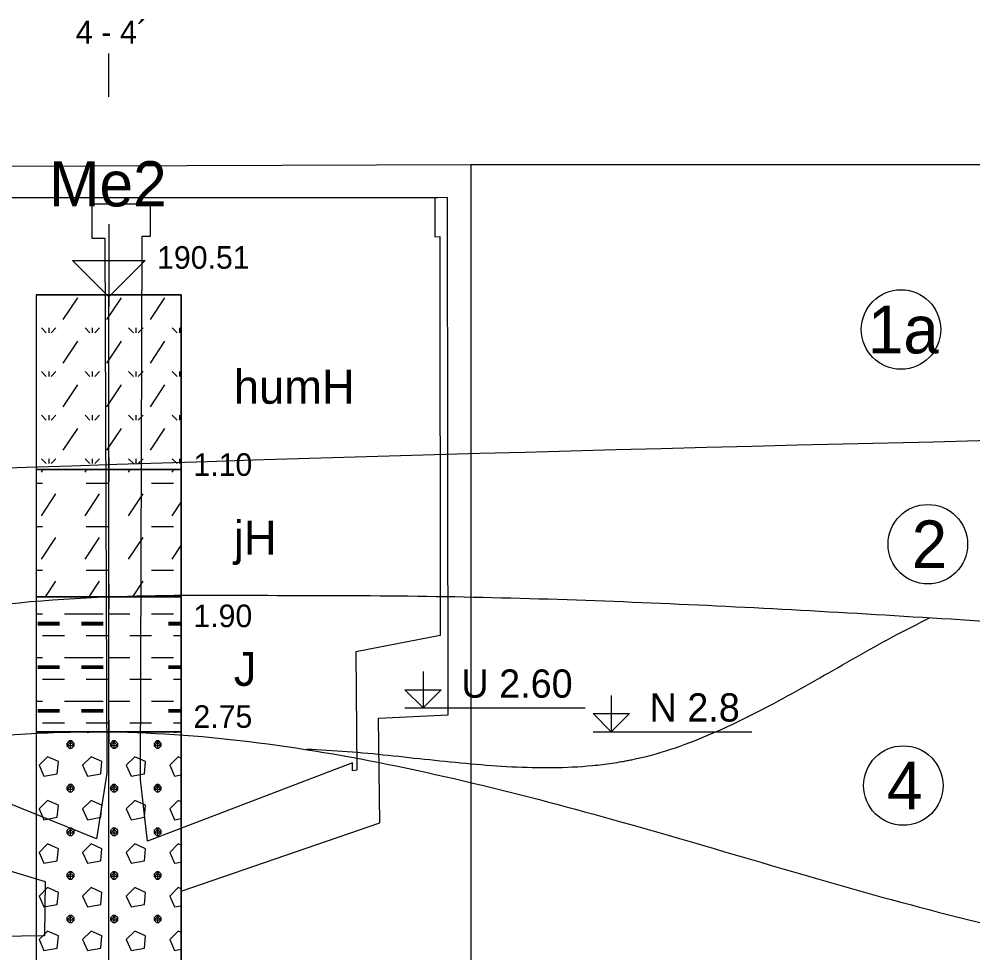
# Model space of a CAD drawing. Extents: x 3042 to 4120, y 576 to 2694.
# Drawn here: x 3378.17 to 3408.18, y 1288.39 to 1317.77 of the extents above; entities that cross this region are included whole.
import ezdxf

# ---------------------------------------------------------------- set-up
doc = ezdxf.new("R2010")
doc.units = 0
for name, color, linetype in [('15', 7, 'Continuous'), ('16', 7, 'Continuous'), ('17', 7, 'Continuous'), ('18', 7, 'Continuous'), ('22', 7, 'Continuous'), ('51', 7, 'Continuous'), ('52', 7, 'Continuous'), ('53', 7, 'Continuous'), ('56', 7, 'Continuous'), ('61', 7, 'Continuous'), ('komunikace', 7, 'Continuous'), ('nádrže', 7, 'Continuous'), ('pomocna', 7, 'Continuous'), ('rozhraní', 7, 'Continuous')]:
    doc.layers.add(name, color=color, linetype=linetype)

msp = doc.modelspace()

# ---------------------------------------------------------------- linework, layer by layer
at = {"layer": '15'}
msp.add_lwpolyline([(3380.987, 1311.318), (3380.987, 1309.032), (3379.844, 1310.175), (3382.13, 1310.175), (3380.987, 1309.032)], dxfattribs=at)
at = {"layer": '18'}
msp.add_line((3380.987, 1272.595), (3380.987, 1309.095), dxfattribs=at)
at = {"layer": '22'}
msp.add_lwpolyline([(3380.987, 1315.318), (3380.987, 1315.318), (3380.987, 1316.687)], dxfattribs=at)
at = {"layer": '51'}
for p, q in [((3379.557, 1308.316), (3380.014, 1309.002)), ((3380.928, 1308.316), (3381.386, 1309.002)), ((3382.3, 1308.316), (3382.757, 1309.002)), ((3378.871, 1308.049), (3379.023, 1307.897)), ((3379.1, 1308.049), (3379.1, 1307.897)), ((3379.328, 1308.049), (3379.176, 1307.897)), ((3380.243, 1308.049), (3380.395, 1307.897)), ((3380.471, 1308.049), (3380.471, 1307.897)), ((3380.7, 1308.049), (3380.547, 1307.897)), ((3381.614, 1308.049), (3381.767, 1307.897)), ((3381.843, 1308.049), (3381.843, 1307.897)), ((3382.071, 1308.049), (3381.919, 1307.897)), ((3382.986, 1308.049), (3383.138, 1307.897)), ((3383.214, 1308.049), (3383.214, 1307.897)), ((3379.557, 1306.944), (3380.014, 1307.63)), ((3380.928, 1306.944), (3381.386, 1307.63)), ((3382.3, 1306.944), (3382.757, 1307.63)), ((3378.871, 1306.678), (3379.023, 1306.525)), ((3379.1, 1306.678), (3379.1, 1306.525)), ((3379.328, 1306.678), (3379.176, 1306.525)), ((3380.243, 1306.678), (3380.395, 1306.525)), ((3380.471, 1306.678), (3380.471, 1306.525)), ((3380.7, 1306.678), (3380.547, 1306.525)), ((3381.614, 1306.678), (3381.767, 1306.525)), ((3381.843, 1306.678), (3381.843, 1306.525)), ((3382.071, 1306.678), (3381.919, 1306.525)), ((3382.986, 1306.678), (3383.138, 1306.525)), ((3383.214, 1306.678), (3383.214, 1306.525)), ((3379.557, 1305.573), (3380.014, 1306.258)), ((3380.928, 1305.573), (3381.386, 1306.258)), ((3382.3, 1305.573), (3382.757, 1306.258)), ((3378.871, 1305.306), (3379.023, 1305.154)), ((3379.1, 1305.306), (3379.1, 1305.154)), ((3379.328, 1305.306), (3379.176, 1305.154)), ((3380.243, 1305.306), (3380.395, 1305.154)), ((3380.471, 1305.306), (3380.471, 1305.154)), ((3380.7, 1305.306), (3380.547, 1305.154)), ((3381.614, 1305.306), (3381.767, 1305.154)), ((3381.843, 1305.306), (3381.843, 1305.154)), ((3382.071, 1305.306), (3381.919, 1305.154)), ((3382.986, 1305.306), (3383.138, 1305.154)), ((3383.214, 1305.306), (3383.214, 1305.154)), ((3379.557, 1304.201), (3380.014, 1304.887)), ((3380.928, 1304.201), (3381.386, 1304.887)), ((3382.3, 1304.201), (3382.757, 1304.887)), ((3378.871, 1303.934), (3379.023, 1303.782)), ((3379.1, 1303.934), (3379.1, 1303.782)), ((3379.328, 1303.934), (3379.176, 1303.782)), ((3380.243, 1303.934), (3380.395, 1303.782)), ((3380.471, 1303.934), (3380.471, 1303.782)), ((3380.7, 1303.934), (3380.547, 1303.782)), ((3381.614, 1303.934), (3381.767, 1303.782)), ((3381.843, 1303.934), (3381.843, 1303.782)), ((3382.071, 1303.934), (3381.919, 1303.782)), ((3382.986, 1303.934), (3383.138, 1303.782)), ((3383.214, 1303.934), (3383.214, 1303.782)), ((3378.871, 1303.515), (3378.924, 1303.595)), ((3380.243, 1303.515), (3380.296, 1303.595)), ((3381.614, 1303.515), (3381.668, 1303.595)), ((3382.986, 1303.515), (3383.039, 1303.595)), ((3378.701, 1303.172), (3378.909, 1303.172)), ((3380.281, 1303.172), (3380.967, 1303.172)), ((3382.338, 1303.172), (3383.024, 1303.172)), ((3378.871, 1302.144), (3379.328, 1302.829)), ((3380.243, 1302.144), (3380.7, 1302.829)), ((3381.614, 1302.144), (3382.071, 1302.829)), ((3382.986, 1302.144), (3383.273, 1302.574)), ((3378.701, 1301.801), (3378.909, 1301.801)), ((3380.281, 1301.801), (3380.967, 1301.801)), ((3382.338, 1301.801), (3383.024, 1301.801)), ((3378.871, 1300.772), (3379.328, 1301.458)), ((3380.243, 1300.772), (3380.7, 1301.458)), ((3381.614, 1300.772), (3382.071, 1301.458)), ((3382.986, 1300.772), (3383.273, 1301.202)), ((3378.701, 1300.429), (3378.909, 1300.429)), ((3380.281, 1300.429), (3380.967, 1300.429)), ((3382.338, 1300.429), (3383.024, 1300.429)), ((3379.001, 1299.595), (3379.328, 1300.086)), ((3380.373, 1299.595), (3380.7, 1300.086)), ((3381.744, 1299.595), (3382.071, 1300.086)), ((3378.701, 1299.058), (3378.909, 1299.058)), ((3379.595, 1299.058), (3380.281, 1299.058)), ((3380.128, 1299.058), (3380.814, 1299.058)), ((3380.967, 1299.058), (3381.652, 1299.058)), ((3382.338, 1299.058), (3383.024, 1299.058)), ((3378.757, 1298.791), (3379.443, 1298.791)), ((3378.757, 1298.753), (3379.443, 1298.753)), ((3378.757, 1298.715), (3379.443, 1298.715)), ((3380.128, 1298.791), (3380.814, 1298.791)), ((3380.128, 1298.753), (3380.814, 1298.753)), ((3380.128, 1298.715), (3380.814, 1298.715)), ((3382.872, 1298.791), (3383.273, 1298.791)), ((3382.872, 1298.753), (3383.273, 1298.753)), ((3382.872, 1298.715), (3383.273, 1298.715)), ((3378.909, 1298.372), (3379.595, 1298.372)), ((3380.281, 1298.372), (3380.967, 1298.372)), ((3381.652, 1298.372), (3382.338, 1298.372)), ((3383.024, 1298.372), (3383.273, 1298.372)), ((3378.701, 1297.686), (3378.909, 1297.686)), ((3379.595, 1297.686), (3380.281, 1297.686)), ((3380.128, 1297.686), (3380.814, 1297.686)), ((3380.967, 1297.686), (3381.652, 1297.686)), ((3382.338, 1297.686), (3383.024, 1297.686)), ((3378.757, 1297.419), (3379.443, 1297.419)), ((3378.757, 1297.381), (3379.443, 1297.381)), ((3378.757, 1297.343), (3379.443, 1297.343)), ((3380.128, 1297.419), (3380.814, 1297.419)), ((3380.128, 1297.381), (3380.814, 1297.381)), ((3380.128, 1297.343), (3380.814, 1297.343)), ((3382.872, 1297.419), (3383.273, 1297.419)), ((3382.872, 1297.381), (3383.273, 1297.381)), ((3382.872, 1297.343), (3383.273, 1297.343)), ((3378.909, 1297), (3379.595, 1297)), ((3380.281, 1297), (3380.967, 1297)), ((3381.652, 1297), (3382.338, 1297)), ((3383.024, 1297), (3383.273, 1297)), ((3378.701, 1296.314), (3378.909, 1296.314)), ((3379.595, 1296.314), (3380.281, 1296.314)), ((3380.128, 1296.314), (3380.814, 1296.314)), ((3380.967, 1296.314), (3381.652, 1296.314)), ((3382.338, 1296.314), (3383.024, 1296.314)), ((3378.757, 1296.048), (3379.443, 1296.048)), ((3378.757, 1296.01), (3379.443, 1296.01)), ((3380.128, 1296.048), (3380.814, 1296.048)), ((3380.128, 1296.01), (3380.814, 1296.01)), ((3382.872, 1296.048), (3383.273, 1296.048)), ((3382.872, 1296.01), (3383.273, 1296.01)), ((3378.757, 1295.971), (3379.443, 1295.971)), ((3380.128, 1295.971), (3380.814, 1295.971)), ((3382.872, 1295.971), (3383.273, 1295.971)), ((3378.909, 1295.629), (3379.595, 1295.629)), ((3380.281, 1295.629), (3380.967, 1295.629)), ((3381.652, 1295.629), (3382.338, 1295.629)), ((3383.024, 1295.629), (3383.273, 1295.629)), ((3379.785, 1294.828), (3379.785, 1295.057)), ((3381.157, 1294.828), (3381.157, 1295.057)), ((3382.529, 1294.828), (3382.529, 1295.057)), ((3379.785, 1293.457), (3379.785, 1293.685)), ((3381.157, 1293.457), (3381.157, 1293.685)), ((3382.529, 1293.457), (3382.529, 1293.685)), ((3379.785, 1292.085), (3379.785, 1292.314)), ((3381.157, 1292.085), (3381.157, 1292.314)), ((3382.529, 1292.085), (3382.529, 1292.314)), ((3379.785, 1290.714), (3379.785, 1290.942)), ((3381.157, 1290.714), (3381.157, 1290.942)), ((3382.529, 1290.714), (3382.529, 1290.942)), ((3379.785, 1289.342), (3379.785, 1289.571)), ((3381.157, 1289.342), (3381.157, 1289.571)), ((3382.529, 1289.342), (3382.529, 1289.571))]:
    msp.add_line(p, q, dxfattribs=at)
for points in [[(3378.701, 1303.595), (3383.273, 1303.595), (3383.273, 1309.095), (3378.701, 1309.095)], [(3378.701, 1299.595), (3383.273, 1299.595), (3383.273, 1303.595), (3378.701, 1303.595)], [(3378.701, 1295.345), (3383.273, 1295.345), (3383.273, 1299.595), (3378.701, 1299.595)], [(3378.701, 1277.595), (3383.273, 1277.595), (3383.273, 1295.345), (3378.701, 1295.345)]]:
    msp.add_lwpolyline(points, close=True, dxfattribs=at)
for points in [[(3378.938, 1295.345), (3378.947, 1295.324), (3379.066, 1295.345)], [(3380.309, 1295.345), (3380.319, 1295.324), (3380.438, 1295.345)], [(3381.681, 1295.345), (3381.69, 1295.324), (3381.81, 1295.345)], [(3383.052, 1295.345), (3383.062, 1295.324), (3383.181, 1295.345)], [(3379.747, 1295.057), (3379.671, 1294.981), (3379.671, 1294.905), (3379.747, 1294.828), (3379.824, 1294.828), (3379.9, 1294.905), (3379.9, 1294.981), (3379.824, 1295.057), (3379.747, 1295.057), (3379.9, 1294.905), (3379.671, 1294.905), (3379.824, 1295.057)], [(3381.119, 1295.057), (3381.043, 1294.981), (3381.043, 1294.905), (3381.119, 1294.828), (3381.195, 1294.828), (3381.271, 1294.905), (3381.271, 1294.981), (3381.195, 1295.057), (3381.119, 1295.057), (3381.271, 1294.905), (3381.043, 1294.905), (3381.195, 1295.057)], [(3382.491, 1295.057), (3382.414, 1294.981), (3382.414, 1294.905), (3382.491, 1294.828), (3382.567, 1294.828), (3382.643, 1294.905), (3382.643, 1294.981), (3382.567, 1295.057), (3382.491, 1295.057), (3382.643, 1294.905), (3382.414, 1294.905), (3382.567, 1295.057)], [(3378.795, 1294.295), (3378.947, 1293.952), (3379.366, 1294.028), (3379.404, 1294.409), (3379.062, 1294.562), (3378.795, 1294.295)], [(3380.166, 1294.295), (3380.319, 1293.952), (3380.738, 1294.028), (3380.776, 1294.409), (3380.433, 1294.562), (3380.166, 1294.295)], [(3381.538, 1294.295), (3381.69, 1293.952), (3382.11, 1294.028), (3382.148, 1294.409), (3381.805, 1294.562), (3381.538, 1294.295)], [(3383.273, 1294.519), (3383.176, 1294.562), (3382.91, 1294.295)], [(3382.91, 1294.295), (3383.062, 1293.952), (3383.273, 1293.99)], [(3379.747, 1293.685), (3379.671, 1293.609), (3379.671, 1293.533), (3379.747, 1293.457), (3379.824, 1293.457), (3379.9, 1293.533), (3379.9, 1293.609), (3379.824, 1293.685), (3379.747, 1293.685), (3379.9, 1293.533), (3379.671, 1293.533), (3379.824, 1293.685)], [(3381.119, 1293.685), (3381.043, 1293.609), (3381.043, 1293.533), (3381.119, 1293.457), (3381.195, 1293.457), (3381.271, 1293.533), (3381.271, 1293.609), (3381.195, 1293.685), (3381.119, 1293.685), (3381.271, 1293.533), (3381.043, 1293.533), (3381.195, 1293.685)], [(3382.491, 1293.685), (3382.414, 1293.609), (3382.414, 1293.533), (3382.491, 1293.457), (3382.567, 1293.457), (3382.643, 1293.533), (3382.643, 1293.609), (3382.567, 1293.685), (3382.491, 1293.685), (3382.643, 1293.533), (3382.414, 1293.533), (3382.567, 1293.685)], [(3378.795, 1292.923), (3378.947, 1292.581), (3379.366, 1292.657), (3379.404, 1293.038), (3379.062, 1293.19), (3378.795, 1292.923)], [(3380.166, 1292.923), (3380.319, 1292.581), (3380.738, 1292.657), (3380.776, 1293.038), (3380.433, 1293.19), (3380.166, 1292.923)], [(3381.538, 1292.923), (3381.69, 1292.581), (3382.11, 1292.657), (3382.148, 1293.038), (3381.805, 1293.19), (3381.538, 1292.923)], [(3383.273, 1293.147), (3383.176, 1293.19), (3382.91, 1292.923)], [(3382.91, 1292.923), (3383.062, 1292.581), (3383.273, 1292.619)], [(3379.747, 1292.314), (3379.671, 1292.238), (3379.671, 1292.161), (3379.747, 1292.085), (3379.824, 1292.085), (3379.9, 1292.161), (3379.9, 1292.238), (3379.824, 1292.314), (3379.747, 1292.314), (3379.9, 1292.161), (3379.671, 1292.161), (3379.824, 1292.314)], [(3381.119, 1292.314), (3381.043, 1292.238), (3381.043, 1292.161), (3381.119, 1292.085), (3381.195, 1292.085), (3381.271, 1292.161), (3381.271, 1292.238), (3381.195, 1292.314), (3381.119, 1292.314), (3381.271, 1292.161), (3381.043, 1292.161), (3381.195, 1292.314)], [(3382.491, 1292.314), (3382.414, 1292.238), (3382.414, 1292.161), (3382.491, 1292.085), (3382.567, 1292.085), (3382.643, 1292.161), (3382.643, 1292.238), (3382.567, 1292.314), (3382.491, 1292.314), (3382.643, 1292.161), (3382.414, 1292.161), (3382.567, 1292.314)], [(3378.795, 1291.552), (3378.947, 1291.209), (3379.366, 1291.285), (3379.404, 1291.666), (3379.062, 1291.819), (3378.795, 1291.552)], [(3380.166, 1291.552), (3380.319, 1291.209), (3380.738, 1291.285), (3380.776, 1291.666), (3380.433, 1291.819), (3380.166, 1291.552)], [(3381.538, 1291.552), (3381.69, 1291.209), (3382.11, 1291.285), (3382.148, 1291.666), (3381.805, 1291.819), (3381.538, 1291.552)], [(3383.273, 1291.776), (3383.176, 1291.819), (3382.91, 1291.552)], [(3382.91, 1291.552), (3383.062, 1291.209), (3383.273, 1291.247)], [(3379.747, 1290.942), (3379.671, 1290.866), (3379.671, 1290.79), (3379.747, 1290.714), (3379.824, 1290.714), (3379.9, 1290.79), (3379.9, 1290.866), (3379.824, 1290.942), (3379.747, 1290.942), (3379.9, 1290.79), (3379.671, 1290.79), (3379.824, 1290.942)], [(3381.119, 1290.942), (3381.043, 1290.866), (3381.043, 1290.79), (3381.119, 1290.714), (3381.195, 1290.714), (3381.271, 1290.79), (3381.271, 1290.866), (3381.195, 1290.942), (3381.119, 1290.942), (3381.271, 1290.79), (3381.043, 1290.79), (3381.195, 1290.942)], [(3382.491, 1290.942), (3382.414, 1290.866), (3382.414, 1290.79), (3382.491, 1290.714), (3382.567, 1290.714), (3382.643, 1290.79), (3382.643, 1290.866), (3382.567, 1290.942), (3382.491, 1290.942), (3382.643, 1290.79), (3382.414, 1290.79), (3382.567, 1290.942)], [(3378.795, 1290.18), (3378.947, 1289.837), (3379.366, 1289.914), (3379.404, 1290.295), (3379.062, 1290.447), (3378.795, 1290.18)], [(3380.166, 1290.18), (3380.319, 1289.837), (3380.738, 1289.914), (3380.776, 1290.295), (3380.433, 1290.447), (3380.166, 1290.18)], [(3381.538, 1290.18), (3381.69, 1289.837), (3382.11, 1289.914), (3382.148, 1290.295), (3381.805, 1290.447), (3381.538, 1290.18)], [(3383.273, 1290.404), (3383.176, 1290.447), (3382.91, 1290.18)], [(3382.91, 1290.18), (3383.062, 1289.837), (3383.273, 1289.876)], [(3379.747, 1289.571), (3379.671, 1289.494), (3379.671, 1289.418), (3379.747, 1289.342), (3379.824, 1289.342), (3379.9, 1289.418), (3379.9, 1289.494), (3379.824, 1289.571), (3379.747, 1289.571), (3379.9, 1289.418), (3379.671, 1289.418), (3379.824, 1289.571)], [(3381.119, 1289.571), (3381.043, 1289.494), (3381.043, 1289.418), (3381.119, 1289.342), (3381.195, 1289.342), (3381.271, 1289.418), (3381.271, 1289.494), (3381.195, 1289.571), (3381.119, 1289.571), (3381.271, 1289.418), (3381.043, 1289.418), (3381.195, 1289.571)], [(3382.491, 1289.571), (3382.414, 1289.494), (3382.414, 1289.418), (3382.491, 1289.342), (3382.567, 1289.342), (3382.643, 1289.418), (3382.643, 1289.494), (3382.567, 1289.571), (3382.491, 1289.571), (3382.643, 1289.418), (3382.414, 1289.418), (3382.567, 1289.571)], [(3378.795, 1288.809), (3378.947, 1288.466), (3379.366, 1288.542), (3379.404, 1288.923), (3379.062, 1289.075), (3378.795, 1288.809)], [(3380.166, 1288.809), (3380.319, 1288.466), (3380.738, 1288.542), (3380.776, 1288.923), (3380.433, 1289.075), (3380.166, 1288.809)], [(3381.538, 1288.809), (3381.69, 1288.466), (3382.11, 1288.542), (3382.148, 1288.923), (3381.805, 1289.075), (3381.538, 1288.809)], [(3383.273, 1289.033), (3383.176, 1289.075), (3382.91, 1288.809)], [(3382.91, 1288.809), (3383.062, 1288.466), (3383.273, 1288.504)]]:
    msp.add_lwpolyline(points, dxfattribs=at)
at = {"layer": '53'}
for p, q in [((3378.701, 1309.095), (3378.701, 1272.595)), ((3378.701, 1309.095), (3383.273, 1309.095)), ((3383.273, 1309.095), (3383.273, 1272.595)), ((3378.701, 1303.595), (3383.273, 1303.595)), ((3378.701, 1299.595), (3383.273, 1299.595)), ((3378.701, 1295.345), (3383.273, 1295.345))]:
    msp.add_line(p, q, dxfattribs=at)
at = {"layer": '56'}
for p, q in [((3380.987, 1309.476), (3380.987, 1308.714)), ((3380.606, 1309.095), (3381.368, 1309.095)), ((3380.987, 1303.976), (3380.987, 1303.214)), ((3380.606, 1303.595), (3381.368, 1303.595)), ((3380.987, 1299.976), (3380.987, 1299.214)), ((3380.606, 1299.595), (3381.368, 1299.595)), ((3380.987, 1295.726), (3380.987, 1294.964)), ((3380.606, 1295.345), (3381.368, 1295.345))]:
    msp.add_line(p, q, dxfattribs=at)
at = {"layer": '61'}
for p, q in [((3390.306, 1296.095), (3395.979, 1296.095)), ((3396.227, 1295.345), (3401.222, 1295.345))]:
    msp.add_line(p, q, dxfattribs=at)
for points in [[(3390.878, 1297.238), (3390.878, 1296.095), (3390.306, 1296.667), (3391.449, 1296.667), (3390.878, 1296.095)], [(3396.798, 1296.488), (3396.798, 1295.345), (3396.227, 1295.917), (3397.37, 1295.917), (3396.798, 1295.345)]]:
    msp.add_lwpolyline(points, dxfattribs=at)
at = {"layer": 'komunikace'}
msp.add_line((3392.39, 1313.195), (3433.88, 1313.195), dxfattribs=at)
at = {"layer": 'nádrže'}
msp.add_line((3371.032, 1312.155), (3391.342, 1312.155), dxfattribs=at)
for points in [[(3383.275, 1285.635), (3383.273, 1290.329), (3389.524, 1292.485), (3389.479, 1295.77), (3391.669, 1295.883), (3391.652, 1312.155), (3391.251, 1312.144), (3391.253, 1310.922), (3391.407, 1310.926), (3391.42, 1298.374), (3388.765, 1297.857), (3388.794, 1294.14), (3388.662, 1294.114), (3388.66, 1294.371), (3382.21, 1291.907), (3381.992, 1293.836), (3382.036, 1310.934), (3382.307, 1310.935), (3382.303, 1311.948), (3380.459, 1311.948), (3380.462, 1310.873), (3380.867, 1310.873), (3380.926, 1294.044), (3380.608, 1291.974), (3373.956, 1294.66)], [(3373.292, 1292.361), (3378.988, 1290.634), (3378.968, 1288.926), (3376.792, 1288.892)]]:
    msp.add_lwpolyline(points, dxfattribs=at)
at = {"layer": 'pomocna'}
for p, q in [((3392.39, 1251.545), (3392.39, 1313.195)), ((3392.39, 1313.195), (3433.88, 1313.195))]:
    msp.add_line(p, q, dxfattribs=at)
at = {"layer": 'rozhraní'}
msp.add_line((3365.26, 1313.095), (3392.39, 1313.195), dxfattribs=at)
for centre in [(3405.919, 1308.001), (3406.763, 1301.246), (3405.991, 1293.654)]:
    msp.add_circle(centre, 1.25, dxfattribs=at)
for points in [[(3215.367, 1295.492), (3223.007, 1295.445), (3284.237, 1298.745), (3466.926, 1305.295), (3469.69, 1305.295), (3507.357, 1301.345), (3560.04, 1300.995)], [(3330.077, 1289.291), (3336.607, 1289.345), (3342.253, 1289.807), (3347.822, 1290.949), (3358.825, 1294.38), (3369.814, 1297.856), (3375.365, 1299.054), (3380.987, 1299.595), (3385.695, 1299.64), (3390.406, 1299.619), (3399.821, 1299.325), (3409.251, 1298.784), (3418.647, 1298.095), (3424.692, 1297.433), (3430.738, 1296.484), (3442.828, 1294.299), (3448.859, 1293.371), (3451.886, 1292.998), (3454.918, 1292.687), (3460.963, 1292.471), (3467.007, 1292.795), (3475.291, 1293.755), (3483.553, 1294.967), (3491.821, 1296.12), (3500.124, 1296.9), (3507.357, 1297.345)], [(3387.207, 1294.804), (3388.493, 1294.73), (3389.789, 1294.609), (3392.387, 1294.341), (3394.954, 1294.22), (3396.212, 1294.285), (3396.831, 1294.36), (3397.138, 1294.41), (3397.291, 1294.439), (3397.368, 1294.454), (3397.444, 1294.469), (3399.862, 1295.246), (3402.203, 1296.396), (3404.512, 1297.699), (3405.668, 1298.34), (3406.834, 1298.937)], [(3271.345, 1282.999), (3284.237, 1284.245), (3297.343, 1284.894), (3310.501, 1285.162), (3323.62, 1285.371), (3336.607, 1285.845), (3347.74, 1287.702), (3358.827, 1290.97), (3369.9, 1294.05), (3375.439, 1295.021), (3378.212, 1295.276), (3380.987, 1295.345), (3390.374, 1294.201), (3399.75, 1291.756), (3409.16, 1289.169), (3418.647, 1287.595), (3430.693, 1286.786), (3442.786, 1286.102), (3454.9, 1285.59), (3467.007, 1285.295), (3487.184, 1285.301), (3497.273, 1285.651), (3507.357, 1286.345), (3512.194, 1287.141), (3526.536, 1295.496), (3547.897, 1291.945), (3557.186, 1291.945)]]:
    msp.add_spline(points, degree=3, dxfattribs=at)

# ---------------------------------------------------------------- texts
at = {"layer": '16'}
msp.add_text('Me2', height=1.4224, dxfattribs=at).set_placement((3379.113, 1311.874))
at = {"layer": '17'}
msp.add_text('190.51', height=0.7112, dxfattribs=at).set_placement((3382.511, 1309.913))
at = {"layer": '22'}
msp.add_text('4 - 4´', height=0.72, dxfattribs=at).set_placement((3379.951, 1316.996))
at = {"layer": '52'}
for s, height, p in [('humH', 1.0668, (3384.924, 1305.667)), ('1.10', 0.7112, (3383.654, 1303.397)), ('jH', 1.0668, (3384.924, 1300.917)), ('1.90', 0.7112, (3383.654, 1298.638)), ('J', 1.067, (3384.924, 1296.792)), ('2.75', 0.7112, (3383.654, 1295.471))]:
    msp.add_text(s, height=height, dxfattribs=at).set_placement(p)
at = {"layer": '61'}
for s, p in [('U 2.60', (3392.084, 1296.419)), ('N 2.8', (3398.005, 1295.669))]:
    msp.add_text(s, height=0.889, dxfattribs=at).set_placement(p)
at = {"layer": 'rozhraní'}
for s, p in [('1a', (3404.876, 1307.251)), ('2', (3406.255, 1300.496)), ('4', (3405.475, 1292.904))]:
    msp.add_text(s, height=1.5, dxfattribs=at).set_placement(p)

doc.saveas('drawing.dxf')
